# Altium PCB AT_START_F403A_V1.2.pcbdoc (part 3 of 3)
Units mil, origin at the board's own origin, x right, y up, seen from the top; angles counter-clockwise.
Board outline 5262.73 x 3522.74 mil, 2 copper layers (Top Layer, Bottom Layer); 135 components, 162 nets, 647 pads, 293 vias.
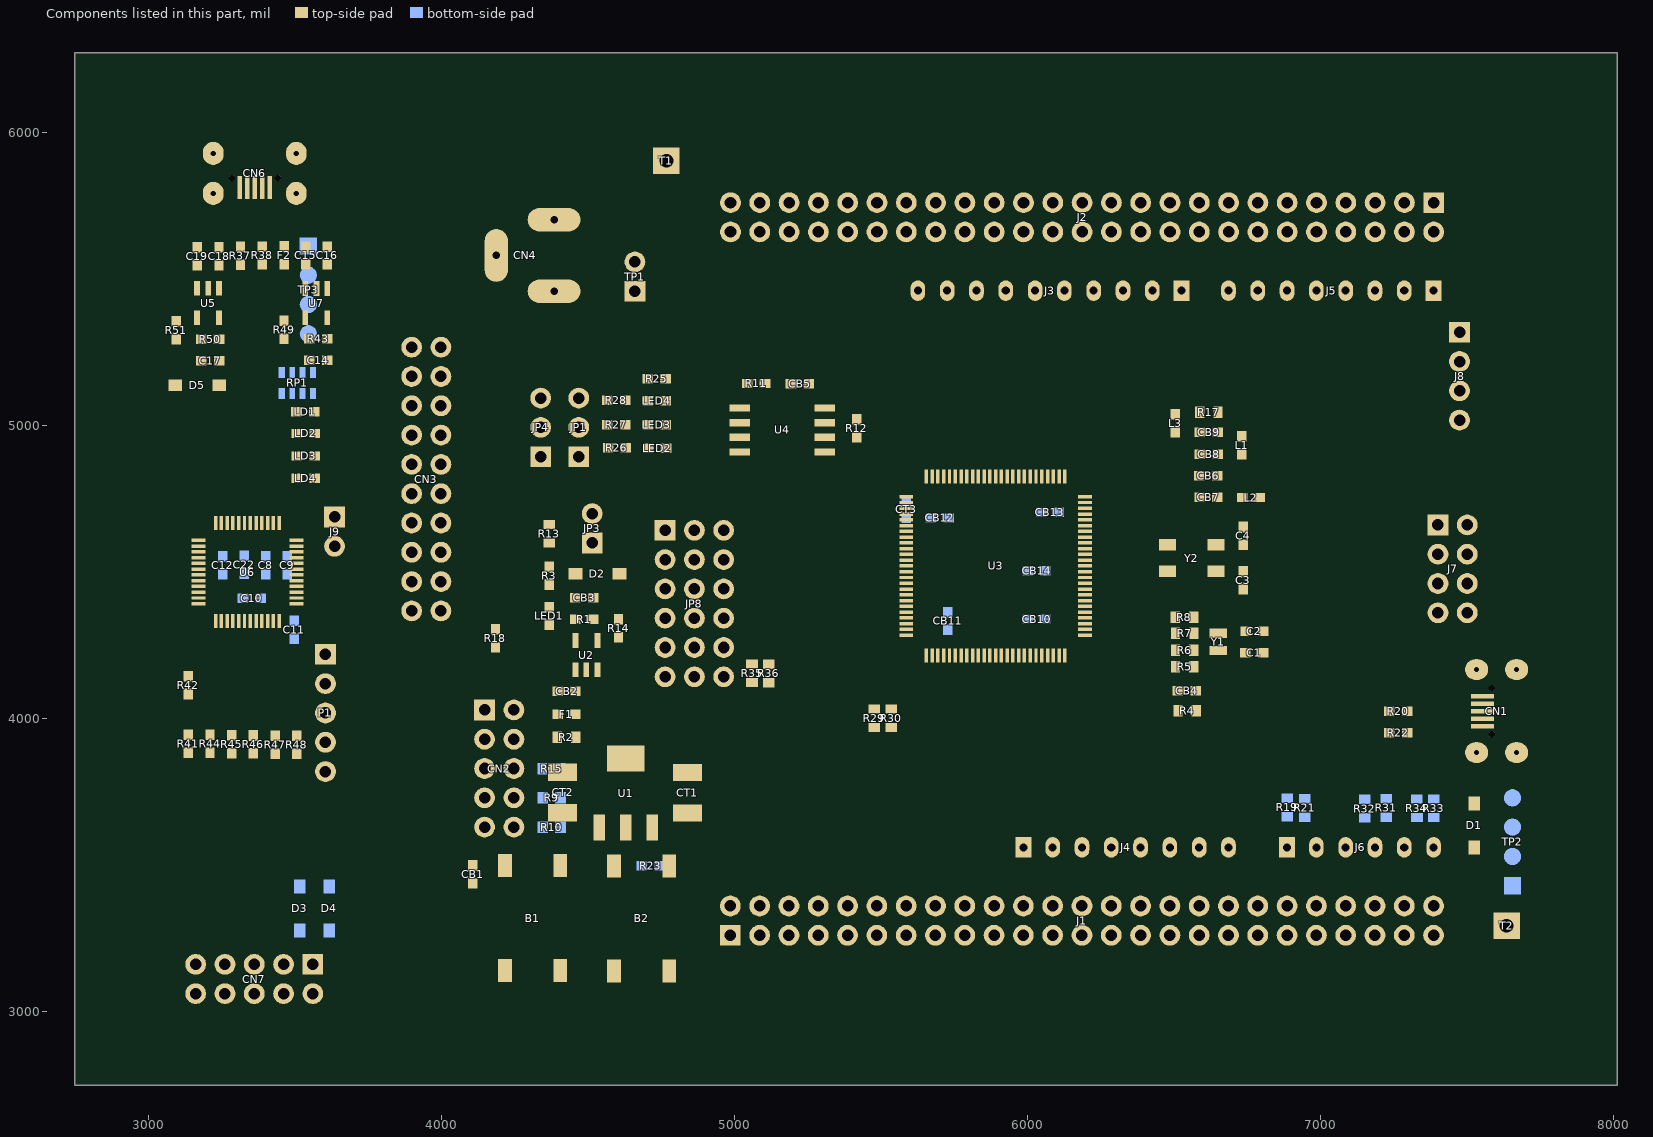
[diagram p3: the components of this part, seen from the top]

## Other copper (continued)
Bottom Layer:
  region net $1N764: 3255.85,5454.34 3480.85,5454.34 3480.85,5486.34 3255.85,5486.34
  region net 5V: 4998.13,3683.74 4993.99,3703.74 ccw(c4993.99,3674.68) 4981.13,3700.74 4981.13,3686.74 ccw(c4998.13,3733.41)
  region net ATLINK_5V: 3434.05,5682.34 3419.05,5652.34 ccw(c3419.05,5754.59) 3449.05,5656.84 3453.34,5677.84 ccw(c3434.05,5638.75)
  region net VCC: 3484.85,4619.34 cw(c3584.85,4619.34) 3504.85,4679.34 3444.85,4679.34 cw(c3364.85,4619.34) 3464.85,4619.34
  region net 5V: 7501.85,3464.74 7518.92,3453.53 ccw(c7498.37,3474.07) 7525.89,3464.74 7515.99,3474.64 ccw(c7536.97,3429.62)
  region net AVREF+: 6429.99,5591.74 cw(c6379.99,5591.74) 6419.99,5561.74 6449.99,5561.74 cw(c6489.99,5591.74) 6439.99,5591.74
  region net VDD: 5805.99,4571.74 cw(c5905.99,4571.74) 5825.99,4631.74 5765.99,4631.74 cw(c5685.99,4571.74) 5785.99,4571.74
  region net VDD: 5972.99,4687.74 cw(c5930.59,4687.74) 5952.99,4651.74 6012.99,4651.74 cw(c6035.39,4687.74) 5992.99,4687.74
  region net VDD: 4550.99,4690.76 cw(c4550.99,4590.76) 4610.99,4670.76 4610.99,4730.76 cw(c4550.99,4810.76) 4550.99,4710.76
  region net A0: 6907.7,3623.74 cw(c6907.7,3653.74) 6889.7,3629.74 6889.7,3611.74 cw(c6907.7,3587.74) 6907.7,3617.74
  region net JDI: 4987.99,3938.88 4987.43,3938.9 4986.87,3938.95 4986.32,3939.04 4985.79,3939.16 4985.27,3939.32 4984.77,3939.51 4984.3,3939.74 4983.87,3940 4983.46,3940.29 4983.1,3940.63 4982.78,3940.99 4982.51,3941.4 4982.29,3941.83 4982.13,3942.31 4982.03,3942.82 4981.99,3943.36 4975.99,3943.36 4975.92,3941.84 4975.71,3940.23 4975.36,3938.57 4974.88,3936.92 4974.27,3935.31 4973.53,3933.81 4973.12,3933.12 4972.68,3932.47 4972.21,3931.87 4971.71,3931.32 4975.95,3927.08 4977.13,3928.16 4978.48,3929.21 4979.95,3930.19 4981.52,3931.07 4983.14,3931.81 4983.96,3932.12 4984.79,3932.38 4985.6,3932.6 4986.41,3932.75 4987.21,3932.85 4987.99,3932.88
  region net NRST: 4082.83,3733.74 4082.08,3733.77 4081.26,3733.86 4079.51,3734.21 4077.66,3734.75 4075.79,3735.45 4073.96,3736.28 4072.27,3737.21 4070.79,3738.2 4070.15,3738.71 4069.59,3739.23 4065.35,3734.98 4065.86,3734.42 4066.37,3733.79 4067.36,3732.3 4068.29,3730.61 4069.12,3728.79 4069.82,3726.91 4070.36,3725.06 4070.71,3723.31 4070.8,3722.5 4070.83,3721.74 4076.83,3721.74 4076.87,3722.3 4076.97,3722.86 4077.13,3723.41 4077.35,3723.94 4077.62,3724.46 4077.94,3724.96 4078.3,3725.43 4078.71,3725.87 4079.15,3726.27 4079.62,3726.63 4080.11,3726.95 4080.63,3727.22 4081.17,3727.44 4081.71,3727.61 4082.27,3727.71 4082.83,3727.74
  region net VCC: 3390.85,4588.34 3384.85,4573.34 3416.85,4573.34 3410.85,4588.34
  region net VCC: 3446.85,4565.34 3416.85,4573.34 3416.85,4537.34 3446.85,4545.34
  region net VCC: 3520.85,4565.34 3490.85,4573.34 3490.85,4537.34 3520.85,4545.34
  region net VCC: 3464.85,4603.34 3458.85,4573.34 3490.85,4573.34 3484.85,4603.34
  region net VCC: 3428.85,4565.34 3428.85,4545.34 3458.85,4537.34 3458.85,4573.34
  region net VCC: 3313.37,4365.34 3333.37,4365.34 3341.37,4395.34 3305.37,4395.34
  region net VCC: 3275.37,4421.34 3275.37,4401.34 3305.37,4395.34 3305.37,4427.34
  region net VCC: 3452.43,4283.95 3452.43,4263.95 3482.43,4256.08 3482.43,4292.08
  region net VCC: 3488.43,4237.84 3508.43,4237.84 3514.43,4256.08 3482.43,4256.08
  region net VCC: 3243.85,4603.34 3237.85,4573.34 3269.85,4573.34 3263.85,4603.34
  region net 3V3: 3551.37,3227.77 3526.41,3197.77 3596.37,3197.77 3571.37,3227.77
  region net NRST: 3288.42,3185.78 3264.85,3222.58 3258.85,3222.58 3235.27,3185.78
  region net ATLK_TX: 3297.21,3060.12 3306.56,3102.81 3302.32,3107.05 3259.63,3097.7
  region net ATLK_RX: 3197.21,3060.12 3206.56,3102.81 3202.32,3107.05 3159.63,3097.7
  region net 3V3: 3607.37,3381.06 3627.37,3381.06 3637.05,3404.43 3597.68,3404.43
  region net 3V3: 3607.37,3481.68 3597.68,3451.68 3637.05,3451.68 3627.37,3481.68
  region net VCC: 3570.41,4699.34 3570.41,4679.34 3600.41,4654.34 3600.41,4724.34
  region net VCC: 3539.41,4230.34 3539.41,4210.34 3569.41,4185.34 3569.41,4255.34
  region net VCC: 3594.85,4285.77 3569.85,4255.77 3639.85,4255.77 3614.85,4285.77
  region net M-NRST: 3640.21,3918.12 3649.56,3960.81 3645.32,3965.05 3602.63,3955.7
  region net VCC: 3491.37,5193.06 3466.76,5201.76 3466.76,5164.35 3491.37,5173.06
  region net VCC: 3455.94,5193.06 3455.94,5173.06 3481.53,5164.35 3481.53,5201.76
  region net VCC: 3526.8,5193.06 3501.21,5201.76 3501.21,5164.35 3526.8,5173.06
  region net VCC: 3562.23,5193.06 3536.64,5201.76 3536.64,5164.35 3562.23,5173.06
  region net VCC: 3491.37,5193.06 3491.37,5173.06 3516.96,5164.35 3516.96,5201.76
  region net VCC: 3603.06,5193.06 3573.06,5201.76 3573.06,5164.35 3603.06,5173.06
  region net VCC: 3526.8,5193.06 3526.8,5173.06 3551.41,5164.35 3551.41,5201.76
  region net $1N750: 3452.94,5082.52 3458.94,5082.52 3466.44,5091.52 3445.44,5091.52
  region net $1N751: 3488.37,5082.52 3494.37,5082.52 3501.21,5091.52 3481.53,5091.52
  region net $1N752: 3523.8,5082.52 3529.8,5082.52 3536.64,5091.52 3516.96,5091.52
  region net $1N753: 3559.23,5082.52 3565.23,5082.52 3572.73,5091.52 3551.73,5091.52
  region net ATLINK_5V: 3483.43,5629.34 3483.43,5599.34 3516.9,5584.81 3516.9,5643.87
  region net USBM: 3565.96,5492.19 3593.43,5511.34 3593.43,5517.34 3565.96,5536.49
  region net USBP: 3564.35,5390.88 3596.39,5409.27 3596.81,5415.27 3567.46,5435.06
  region net VBUS: 7596.46,3441.06 7596.46,3421.06 7626.46,3401.21 7626.46,3460.27
  region net USB_M: 7636.46,3552.89 7605.79,3533.74 7605.79,3527.74 7636.46,3508.59
  region net USB_P: 7636.46,3652.89 7605.79,3633.74 7605.79,3627.74 7636.46,3608.59
  region net D2: 4434.08,3733.59 4425.08,3741.09 4425.08,3720.09 4434.08,3727.59
  region net ATLK_TX: 4318.84,3733.74 4318.84,3727.74 4327.84,3720.24 4327.84,3741.24
  region net D8: 4434.08,3633.74 4425.08,3641.24 4425.08,3620.24 4434.08,3627.74
  region net ATLK_RX: 4318.84,3633.74 4318.84,3627.74 4327.84,3620.24 4327.84,3641.24
  region net 5V: 4274.57,4054.18 4257.99,4074.43 4237.99,4074.43 4221.42,4054.18
  region net JTMS: 4124.55,3957.32 4088.99,3933.74 4088.99,3927.74 4124.55,3904.17
  region net JTMS: 4183.35,3928.52 4192.71,3971.21 4188.46,3975.45 4145.77,3966.1
  region net BOOT0: 4215.47,3944.8 4195.93,3899.9 4198.65,3894.13 4238.1,3896.72
  region net BOOT0: 4271.43,3904.17 4299.99,3927.74 4299.99,3933.74 4271.43,3957.32
  region net JTCK: 4124.55,3857.32 4087.75,3833.74 4087.75,3827.74 4124.55,3804.17
  region net JTCK: 4182.49,3822.64 4196.43,3866.56 4192.91,3871.52 4151.72,3865.98
  region net SWO: 4270.91,3803.72 4308.17,3827.06 4308.28,3833.06 4271.94,3856.86
  region net NRST: 4124.55,3757.32 4087.75,3733.74 4087.75,3727.74 4124.55,3704.17
  region net ATLK_TX: 4212.63,3732.96 4203.28,3690.27 4207.52,3686.03 4250.21,3695.38
  region net ATLK_TX: 4271.43,3704.17 4308.23,3727.74 4308.23,3733.74 4271.43,3757.32
  region net ATLK_RX: 4271.43,3604.17 4308.23,3627.74 4308.23,3633.74 4271.43,3657.32
  region net PB6: 4837.42,4120.3 4860.99,4100.74 4866.99,4100.74 4890.57,4120.3
  region net PB7: 4861.77,4208.38 4904.46,4199.03 4908.71,4203.27 4899.35,4245.96
  region net PA8: 4899.35,4541.52 4908.71,4584.21 4904.46,4588.45 4861.77,4579.1
  region net PB1_E: 4999.35,4641.52 5008.71,4684.21 5004.46,4688.45 4961.77,4679.1
  region net D7: 4987.05,4516.84 5024.18,4540.24 5024.27,4546.24 4987.8,4569.98
  region net D7: 4987.43,4517.17 5024.23,4540.74 5024.23,4546.74 4987.43,4570.31
  region net PB7_E: 4970.28,4208.87 5010.77,4204.69 5013.97,4209.98 4997.8,4254.34
  region net PB6_E: 4987.43,4117.17 5006.99,4140.74 5006.99,4146.74 4987.43,4170.31
  region net VIN: 4374.99,5389.74 4394.99,5389.74 4419.99,5419.74 4349.99,5419.74
  region net VIN: 4503.72,5469.74 4454.36,5494.74 4454.36,5424.74 4503.72,5449.74
  region net D2: 7451.85,5146.31 7416.99,5122.74 7416.99,5116.74 7451.85,5093.17
  region net VDD: 6110.03,4350.94 6080.03,4356.94 6080.03,4324.94 6110.03,4330.94
  region net VDD: 6072.02,4386.94 6052.02,4386.94 6044.03,4356.94 6080.03,4356.94
  region net VDD: 5774.95,4313.7 5745.2,4321.7 5745.2,4285.7 5774.95,4293.7
  region net VDD: 5683.2,4313.74 5683.2,4293.74 5713.2,4285.7 5713.2,4321.7
  region net VDD: 5660.99,4731.74 5652.99,4701.74 5688.99,4701.74 5680.99,4731.74
  region net VDD: 5660.99,4657.74 5680.99,4657.74 5688.99,4669.74 5652.99,4669.74
  region net VDD: 5625.99,4695.74 5625.99,4675.74 5652.99,4669.74 5652.99,4701.74
  region net VDD: 5999.99,4714.74 5999.99,4694.74 6028.99,4688.74 6028.99,4720.74
  region net VDD: 6036.99,4749.74 6028.99,4720.74 6064.99,4720.74 6056.99,4749.74
  region net VDD: 6110.03,4515.94 6080.03,4521.94 6080.03,4489.94 6110.03,4495.94
  region net VDD: 6052.03,4551.94 6044.03,4521.94 6080.03,4521.94 6072.03,4551.94
  region net VDD: 6072,4459.94 6080.03,4489.94 6044.03,4489.94 6052,4459.94
  region net NRST: 3896.77,4533.38 3939.46,4524.03 3943.71,4528.27 3934.35,4570.96
  region net D3: 3896.77,4633.38 3939.46,4624.03 3943.71,4628.27 3934.35,4670.96
  region net JTCK: 3896.77,4833.38 3939.46,4824.03 3943.71,4828.27 3934.35,4870.96
  region net JTMS: 3896.77,4933.38 3939.46,4924.03 3943.71,4928.27 3934.35,4970.96
  region net JDI: 3934.35,5066.52 3943.71,5109.21 3939.46,5113.45 3896.77,5104.1
  region net D5: 3875.55,5195.31 3848.99,5171.74 3848.99,5165.74 3875.55,5142.17
  region net VDD: 5625.84,4695.89 5603.33,4703.89 5603.33,4667.89 5625.84,4675.89
  region net VDD: 5557.56,4695.74 5557.56,4675.74 5571.33,4667.89 5571.33,4703.89
  region net PB9: 7213.27,3385.03 7189.7,3421.83 7183.7,3421.83 7160.12,3385.03
  region net PB8: 7222.06,3259.37 7231.41,3302.06 7227.17,3306.31 7184.48,3296.95
  region net D4: 6960.12,3238.15 6983.7,3206.04 6989.7,3206.04 7013.27,3238.15
  region net D5: 6884.48,3326.23 6927.17,3316.88 6931.41,3321.12 6922.06,3363.81
  region net D3: 6860.12,3238.15 6883.7,3201.35 6889.7,3201.35 6913.27,3238.15
  region net D3: 6888.91,3296.95 6846.22,3306.31 6841.98,3302.06 6851.33,3259.37
  region net PB2: 5551.76,5764.23 5542.41,5721.54 5546.65,5717.3 5589.34,5726.65
  region net PB1_E: 5660.55,5638.58 5684.12,5601.78 5690.12,5601.78 5713.7,5638.58
  region net D0_RX: 6188.74,5697.41 6146.19,5706.34 6142.02,5702.03 6151.8,5659.2
  region net D1_TX: 6213.41,5785.77 6189.7,5817.44 6183.7,5817.44 6160.27,5785.13
  region net AVREF+: 6384.3,5726.69 6425.69,5715.52 6432.88,5722.47 6422.52,5763.63
  region net NRST: 6784.3,5626.69 6827.13,5616.91 6831.45,5621.08 6822.52,5663.63
  region net PB8: 5623.69,5417.77 5629.69,5417.77 5637.19,5428.9 5616.19,5428.9
  region net PB9: 5723.69,5417.77 5729.69,5417.77 5737.19,5428.9 5716.19,5428.9
  region net AVREF+: 5821.69,5511.08 5809.19,5489.44 5844.19,5489.44 5831.69,5511.08
  region net D12: 6123.69,5417.77 6129.69,5417.77 6137.19,5428.9 6116.19,5428.9
  region net D11: 6223.69,5417.77 6229.69,5417.77 6237.19,5428.9 6216.19,5428.9
  region net D10: 6323.69,5417.77 6329.69,5417.77 6337.19,5428.9 6316.19,5428.9
  region net A0: 6883.7,3605.59 6876.2,3596.59 6897.2,3596.59 6889.7,3605.59
  region net A1: 6983.7,3605.41 6976.2,3594.28 6997.2,3594.28 6989.7,3605.41
  region net A2: 7083.7,3605.41 7076.2,3594.28 7097.2,3594.28 7089.7,3605.41
  region net A3: 7155.39,3579.59 7155.33,3571.16 7161.7,3554.19 7163.85,3581.73
  region net A4: 7260.01,3592.52 7257.03,3587.01 7261.7,3571.74 7271.61,3591.53
  region net A5: 7383.99,3605.44 7376.49,3594.41 7397.49,3594.14 7389.99,3605.37
  region net 5V: 7525.13,4635.59 7547.57,4652.17 7547.57,4672.17 7525.13,4688.74
  region net NRST: 7378.26,4488.74 7341.46,4465.17 7341.46,4459.17 7378.26,4435.59
  region net $3N822: 4680.99,3524.09 4673.49,3515.09 4694.49,3515.09 4686.99,3524.09
  region net $3N822: 4656.99,3502.09 4656.99,3496.09 4665.99,3488.59 4665.99,3509.59
  region net D5: 6883.69,5417.77 6889.69,5417.77 6897.19,5428.9 6876.19,5428.9
  region net D4: 6983.69,5417.77 6989.69,5417.77 6997.19,5428.9 6976.19,5428.9
  region net D3: 7083.69,5417.77 7089.69,5417.77 7097.19,5428.9 7076.19,5428.9
  region net D2: 7183.69,5417.77 7189.69,5417.77 7197.19,5428.9 7176.19,5428.9
  region net D1_TX: 7283.69,5505.41 7276.19,5494.28 7297.19,5494.28 7289.69,5505.41
  region net D0_RX: 7383.69,5505.59 7376.19,5496.59 7397.19,5496.59 7389.69,5505.59
  region net M-NRST: 3324.35,4583.38 3316.85,4574.38 3337.85,4574.38 3330.35,4583.38
  region net 5V: 3506.37,3481.68 3496.68,3451.68 3536.05,3451.68 3526.37,3481.68
  region net ATLINK_5V: 3470.37,3294.06 3470.37,3264.06 3496.68,3254.43 3496.68,3301.68
  region net 3V3: 4504.99,4535.33 4524.99,4535.33 4549.99,4565.33 4479.99,4565.33
  region net VDD: 4538.43,4674.19 4575.23,4690.76 4575.23,4710.76 4538.43,4727.34
  region net VIN: 4595.56,5469.74 4595.56,5449.74 4625.56,5424.74 4625.56,5494.74
  region net VIN: 6676.69,3624.5 6661.69,3571.59 6711.69,3571.59 6696.69,3624.5
  region net 5V: 6376.69,3624.5 6361.69,3571.59 6411.69,3571.59 6396.69,3624.5
  region net 3V3: 6276.69,3508.44 6296.69,3508.44 6311.69,3551.59 6261.69,3551.59
  region net NRST: 6183.69,3605.41 6176.19,3594.28 6197.19,3594.28 6189.69,3605.41
  region net 3V3: 6076.69,3498.68 6096.69,3498.68 6111.69,3551.59 6061.69,3551.59
  region net $1N753: 3463.18,4812.48 3475.45,4818.34 3475.45,4824.34 3463.18,4830.2
  region net $1N752: 3463.18,4888.2 3475.45,4894.06 3475.45,4900.06 3463.18,4905.91
  region net $1N751: 3463.18,4965.39 3475.45,4971.24 3475.45,4977.24 3463.18,4983.1
  region net $1N750: 3464.93,5056.47 3458.94,5068.53 3452.94,5068.31 3447.23,5055.82
  region net M-NRST: 3333.18,4744.2 3345.45,4750.06 3345.45,4756.06 3333.18,4761.91
  region net PB11_E: 5241.64,4781.55 5235.79,4793.82 5229.79,4793.82 5223.93,4781.55
  region net PB11_E: 5238.58,4848.79 5234.05,4835.98 5238.29,4831.74 5251.11,4836.27
  region net PB8: 5274.16,4729.32 5278.69,4742.13 5274.45,4746.37 5261.63,4741.84
  region net PB9: 5270.16,4681.32 5274.69,4694.13 5270.45,4698.37 5257.63,4693.84
  region net M-NRST: 3318.74,4604.06 3324.35,4591.44 3330.35,4591.09 3336.43,4603.02
  region net SPIM_IO3: 5174.52,5011.79 5169.99,4998.98 5174.23,4994.74 5187.05,4999.27
  region net NRST: 5140.37,3649.69 5152.64,3655.55 5152.64,3661.55 5140.37,3667.41
  region net NRST: 5141.4,4064.57 5154.18,4070.06 5154.69,4076.06 5142.9,4082.22
  region net PB9: 6049.18,4031.6 6036.91,4025.74 6036.91,4019.74 6049.18,4013.88
  region net PB11: 5702.99,4901.2 5715.26,4907.06 5715.26,4913.06 5702.99,4918.91
  region net PB1: 5918.88,5038.91 5906.62,5033.06 5906.62,5027.06 5918.88,5021.2
  region net A3: 5952.8,5181.88 5965.07,5187.74 5965.07,5193.74 5952.8,5199.6
  region net PB8: 5070.51,4255.24 5076.37,4242.98 5082.37,4242.98 5088.23,4255.24
  region net PB9: 5102.51,4255.24 5108.37,4242.98 5114.37,4242.98 5120.23,4255.24
  region net D10: 5328.23,4747.87 5322.37,4760.13 5316.37,4760.13 5310.51,4747.87
  region net D9: 5369.54,4505.53 5356.72,4510.06 5352.48,4505.82 5357.01,4493
  region net PA11: 5485.53,4118.25 5497.88,4124.06 5497.97,4130.06 5485.78,4135.97
  region net NRST: 6225.56,4081.91 6213.29,4076.06 6213.29,4070.06 6225.56,4064.2
  region net NRST: 6242.23,4080.87 6236.37,4093.13 6230.37,4093.13 6224.51,4080.87
  region net PA12: 5542.84,4088.25 5555.19,4094.05 5555.27,4100.06 5543.09,4105.97
  region net PA11: 6146.56,4135.91 6134.29,4130.06 6134.29,4124.06 6146.56,4118.2
  region net PA12: 6173.56,4105.91 6161.29,4100.06 6161.29,4094.06 6173.56,4088.2
  region net PB12: 6198.56,4058.6 6186.29,4052.74 6186.29,4046.74 6198.56,4040.88
  region net M-USB_DM: 3350.04,4248.2 3337.77,4242.34 3337.77,4236.34 3350.04,4230.48
  region net NRST: 3300.06,3450.08 3295.53,3437.26 3299.77,3433.02 3312.59,3437.55
  region net ATLK_TX: 3334.06,3419.08 3329.53,3406.26 3333.77,3402.02 3346.59,3406.55
  region net NRST: 3319.66,3629.48 3331.93,3635.34 3331.93,3641.34 3319.66,3647.2
  region net ATLK_TX: 3353.66,3594.48 3365.93,3600.34 3365.93,3606.34 3353.66,3612.2
  region net JTCK: 3144.66,3658.48 3156.93,3664.34 3156.93,3670.34 3144.66,3676.2
  region net JTCK: 3634.59,3640.13 3621.77,3644.66 3617.53,3640.42 3622.06,3627.6
  region net BOOT0: 3292.66,3684.48 3304.93,3690.34 3304.93,3696.34 3292.66,3702.2
  region net BOOT0: 3638.11,3679.84 3625.29,3684.37 3621.05,3680.13 3625.58,3667.32
  region net JTMS: 3218.58,3717.57 3230.84,3723.42 3230.84,3729.42 3218.58,3735.28
  region net M-USB_DP: 3350.04,4205.2 3337.77,4199.34 3337.77,4193.34 3350.04,4187.48
  region net USBP: 3326.64,5709.6 3331.17,5722.42 3326.92,5726.66 3314.11,5722.13
  region net USBM: 3372.24,5701.48 3384.51,5707.34 3384.51,5713.34 3372.24,5719.2
  region net M-USB_DM: 3354.64,5264.08 3350.11,5251.26 3354.35,5247.02 3367.17,5251.55
  region net M-USB_DP: 3321.64,5264.08 3317.11,5251.26 3321.35,5247.02 3334.17,5251.55
  region net D12: 6023.8,5365.88 6036.07,5371.74 6036.07,5377.74 6023.8,5383.6
  region net D11: 6008.8,5330.88 6019.99,5336.74 6019.99,5342.74 6008.8,5348.6
  region net USB_P: 7360.8,4017.88 7373.07,4023.74 7373.07,4029.74 7360.8,4035.6
  region net USB_M: 7350.13,3975.93 7355.99,3963.66 7361.99,3963.66 7367.85,3975.93
  region net PC0: 6698.8,5159.88 6711.07,5165.74 6711.07,5171.74 6698.8,5177.6
  region net PC1: 6644.8,5153.88 6657.07,5159.74 6657.07,5165.74 6644.8,5171.6
  region net A2: 6098.48,5156 6103.01,5168.82 6098.77,5173.06 6085.96,5168.53
  region net A0: 6304.8,5097.88 6316.99,5103.74 6316.99,5109.74 6304.8,5115.6
  region net PB11: 7163.78,4187 7168.31,4199.82 7164.07,4204.06 7151.25,4199.53
  region net PB2: 5242.85,5325.87 5236.99,5338.13 5230.99,5338.13 5225.13,5325.87
  region net NRST: 4225.8,3380.88 4238.07,3386.74 4238.07,3392.74 4225.8,3398.6
  region net NRST: 4828.18,3398.6 4815.91,3392.74 4815.91,3386.74 4828.18,3380.88
  region net $3N822: 4642.8,3490.23 4655.07,3496.09 4655.07,3502.09 4642.8,3507.95
  region net D5: 5887.18,3901.6 5874.91,3895.74 5874.91,3889.74 5887.18,3883.88
  region net BOOT0: 6033.18,3871.6 6020.91,3865.74 6020.91,3859.74 6033.18,3853.88
  region net PD15: 5688.8,4500.88 5701.07,4506.74 5701.07,4512.74 5688.8,4518.6
  region net PD14: 5688.8,4537.88 5701.07,4543.74 5701.07,4549.74 5688.8,4555.6
  region net PD13: 5673.18,4589.97 5660.91,4584.11 5660.91,4578.11 5673.18,4572.25
  region net D8: 6518.18,5297.6 6505.91,5291.74 6505.91,5285.74 6518.18,5279.88
  region net D8: 6533.8,5279.88 6546.07,5285.74 6546.07,5291.74 6533.8,5297.6
  region net D7: 6678.18,5322.6 6665.91,5316.74 6665.91,5310.74 6678.18,5304.88
  region net JDI: 5671.73,3928.53 5658.91,3933.06 5654.67,3928.82 5659.2,3916
  region net AVREF+: 6790.18,5359.6 6777.91,5355.74 6777.91,5345.74 6790.18,5341.88
  region net D8: 7276.18,5314.6 7263.91,5308.74 7263.91,5302.74 7276.18,5296.88
  region net PC3: 6329.66,4950.6 6317.39,4944.74 6317.39,4938.74 6329.66,4932.88
  region net PC1: 6372.18,4906.6 6359.91,4900.74 6359.91,4894.74 6372.18,4888.88
  region net PC0: 6396.18,4882.6 6383.91,4876.74 6383.91,4870.74 6396.18,4864.88
  region net PB15: 7290.18,5192.6 7277.91,5186.74 7277.91,5180.74 7290.18,5174.88
  region net PC13: 6895.8,4130.88 6908.07,4136.74 6908.07,4142.74 6895.8,4148.6
  region net VDD: 6436.42,5052.87 6418.24,5049.74 6418.24,5029.74 6436.42,5026.62
  region net PB14: 7289.91,5224.3 7278.49,5217.93 7279.42,5211.93 7292.63,5206.79
  region net VDD: 6619.42,4040.94 6601.24,4037.82 6601.24,4017.82 6619.42,4014.69
  region net PC1: 6101.8,4590.73 6114.07,4596.58 6114.07,4602.58 6101.8,4608.44
  region net PC3: 6112.8,4651.88 6125.07,4657.74 6125.07,4663.74 6112.8,4669.6
  region net PC2: 6111.8,4619.88 6124.07,4625.74 6124.07,4631.74 6111.8,4637.6
  region net PC0: 6116.8,4564.88 6129.07,4570.74 6129.07,4576.74 6116.8,4582.6
  region net NRST: 5942.23,4301.93 5948.09,4289.66 5954.09,4289.66 5959.94,4301.93
  region net 5V: 7512.02,3475.62 7502.09,3464.98 7516.23,3450.84 7526.87,3460.77
  region net 5V: 7536.49,3484 7535.99,3498.54 7515.99,3498.54 7515.49,3484
  region net SPIM_IO3: 4991.78,4804 4996.31,4816.82 4992.07,4821.06 4979.25,4816.53
  region net PB6: 5954.85,3895.55 5948.99,3907.82 5942.99,3907.82 5937.13,3895.55
  region net PB6_E: 5978.88,3919.6 5966.68,3913.74 5966.68,3907.74 5978.88,3901.88
  region net PB7_E: 6027.85,3931.55 6021.99,3943.82 6015.99,3943.82 6010.13,3931.55
  region net PB8: 6022.18,4006.6 6009.91,4000.74 6009.91,3994.74 6022.18,3988.88
  region net A1: 6280.8,5124.88 6293.07,5130.74 6293.07,5136.74 6280.8,5142.6
  region net D9: 6414.91,5315.18 6410.38,5302.37 6414.62,5298.12 6427.43,5302.66
  region net D6: 6753.2,5292.48 6748.67,5279.66 6752.91,5275.42 6765.73,5279.95
  region net D2: 7178.88,5304.6 7166.62,5298.74 7166.62,5292.74 7178.88,5286.88
  region net PB13: 7270.18,5282.6 7257.91,5276.74 7257.91,5270.74 7270.18,5264.88
  region net D3: 6722.25,3439.95 6735.07,3435.42 6739.31,3439.66 6734.78,3452.48
  region net BOOT0: 4056.58,4179.79 4052.05,4166.98 4056.29,4162.74 4069.11,4167.27
  region net JTMS: 3671.11,3699.84 3658.29,3704.37 3654.05,3700.13 3658.58,3687.32
  region net D2: 5522.56,3848.91 5510.29,3843.06 5510.29,3837.06 5522.56,3831.2
  region net PB7: 5960.21,3964.91 5948.71,3959.06 5948.71,3953.06 5960.21,3947.2
  region net JDI: 4970.13,4048.86 4975.99,4036.6 4981.99,4036.6 4987.85,4048.86
  region net D2: 5453.85,4376.55 5447.99,4388.82 5441.99,4388.82 5436.13,4376.55
  region net D7: 5385.64,4382.91 5373.37,4377.06 5373.37,4371.06 5385.64,4365.2
  region net D7: 5402.31,4381.87 5396.45,4394.13 5390.45,4394.13 5384.59,4381.87
  region net PA8: 5371.05,4421.84 5358.24,4426.37 5353.99,4422.13 5358.53,4409.32
  region net PB13: 5417.23,4769.87 5411.37,4782.13 5405.37,4782.13 5399.51,4769.87
  region net PB14: 5444.23,4736.87 5438.37,4749.13 5432.37,4749.13 5426.51,4736.87
  region net PB15: 5475.23,4710.55 5469.37,4722.82 5463.37,4722.82 5457.51,4710.55
  region net D6: 5623.18,5098.2 5635.45,5104.06 5635.45,5110.06 5623.18,5115.91
  region net PD15: 5512.51,4995.24 5518.37,4982.98 5524.37,4982.98 5530.23,4995.24
  region net PB1: 5451.23,4880.87 5445.37,4893.13 5439.37,4893.13 5433.51,4880.87
  region net PD13: 5454.51,4992.24 5460.37,4979.98 5466.37,4979.98 5472.23,4992.24
  region net PD14: 5483.51,4960.24 5489.37,4947.98 5495.37,4947.98 5501.23,4960.24
  region net D3: 5860.56,3815.91 5848.29,3810.06 5848.29,3804.06 5860.56,3798.2
  region net JTCK: 5641.56,3841.91 5629.29,3836.06 5629.29,3830.06 5641.56,3824.2
  region net JTMS: 5608.56,3897.91 5596.29,3892.06 5596.29,3886.06 5608.56,3880.2
  region net PB12: 5161.18,4026.2 5173.45,4032.06 5173.45,4038.06 5161.18,4043.91
  region net D8: 5461.56,3823.91 5449.29,3818.06 5449.29,3812.06 5461.56,3806.2
  region net LD4: 3147.23,4335.87 3141.37,4348.13 3135.37,4348.13 3129.51,4335.87
  region net LD4: 3129.51,4710.53 3135.37,4698.26 3141.37,4698.26 3147.23,4710.53
  region net SWO: 3173.63,3801.27 3186.45,3796.74 3190.69,3800.98 3186.16,3813.79
  region net SWO: 3175.11,3824.84 3162.29,3829.37 3158.05,3825.13 3162.58,3812.32
  region net SWO: 3127.31,4016.24 3133.16,4003.98 3139.16,4003.98 3145.02,4016.24
  region net SWO: 4031.32,3729.68 4019.06,3723.82 4019.06,3717.82 4031.32,3711.96
  region net ATLK_RX: 3499.04,3539.91 3486.77,3534.05 3486.77,3528.05 3499.04,3522.2

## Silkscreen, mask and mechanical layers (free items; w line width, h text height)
Top Silkscreen Layer:
  drawing of 1272 lines, arcs and shapes, not listed
  text "49" at 4956.37,5940.06 h36
  text "41" at 5362.37,5940.06 h36
  text "31" at 5862.37,5940.06 h36
  text "21" at 6362.37,5940.06 h36
  text "11" at 6865.37,5940.06 h36
  text "1" at 7380.37,5940.06 h36
  text "B10*" at 5066.37,5827.06 h36 r45
  text "E14" at 5166.37,5827.06 h36 r45
  text "E12" at 5266.37,5827.06 h36 r45
  text "E10" at 5366.37,5827.06 h36 r45
  text "E8" at 5471.37,5827.06 h36 r45
  text "B2" at 5571.37,5827.06 h36 r45
  text "B0" at 5671.37,5827.06 h36 r45
  text "A6" at 5871.37,5827.06 h36 r45
  text "A4" at 5971.37,5827.06 h36 r45
  text "A2" at 6171.37,5827.06 h36 r45
  text "A0" at 6271.37,5827.06 h36 r45
  text "NC" at 6476.37,5827.06 h36 r45
  text "NC" at 6771.37,5827.06 h36 r45
  text "E6" at 7171.37,5827.06 h36 r45
  text "E4" at 7271.37,5827.06 h36 r45
  text "E2" at 7371.37,5827.06 h36 r45
  text "GND" at 4971.37,5823.06 h36 r45
  text "C4" at 5771.37,5823.06 h36 r45
  text "GND" at 6071.37,5823.06 h36 r45
  text "C2" at 6571.37,5823.06 h36 r45
  text "C0" at 6671.37,5823.06 h36 r45
  text "C15" at 6971.37,5823.06 h36 r45
  text "C13" at 7071.37,5823.06 h36 r45
  text "VREF" at 6366.37,5819.06 h36 r45
  text "VDD" at 6871.37,5819.06 h36 r45
  text "GND" at 4707.37,5762.06 h48
  text "A1" at 6293.37,5536.06 h36 r45
  text "C1" at 6693.37,5536.06 h36 r45
  text "E9" at 5489.5,5533.06 h36 r45
  text "A3" at 6184.37,5527.06 h36 r45
  text "NC" at 6385.37,5527.06 h36 r45
  text "NC" at 6484.37,5527.06 h36 r45
  text "C3" at 6584.37,5527.06 h36 r45
  text "NC" at 6884.37,5527.06 h36 r45
  text "E3" at 7384.37,5527.06 h36 r45
  text "E7" at 5584.37,5523.06 h36 r45
  text "C5" at 5784.37,5523.06 h36 r45
  text "A7" at 5884.37,5523.06 h36 r45
  text "A5" at 5984.37,5523.06 h36 r45
  text "E5" at 7285.37,5523.06 h36 r45
  text "B1*" at 5670.37,5515.97 h34 r45
  text "NRST" at 6769.37,5515.06 h25 r45
  text "GND" at 6973.37,5515.06 h32 r45
  text "E11" at 5377.37,5514.06 h36 r45
  text "C14" at 7070.37,5514.06 h34 r45
  text "VBAT" at 7169.37,5512.06 h25 r45
  text "VDD" at 6069.37,5508.14 h36 r45
  text "E13" at 5268.37,5506.06 h36 r45
  text "VDD" at 4963.99,5501.79 h36 r45
  text "E15" at 5168.37,5502.06 h36 r45
  text "B11*" at 5062.37,5489.55 h36 r45
  text "50" at 4956.37,5447.29 h36
  text "VIN (7V-12V)" at 4646.37,5443.74 h48 r90
  text "4" at 7011.99,5351.74 h48 r90
  text "8" at 6550.99,5350.74 h48 r90
  text "7" at 6714.99,5350.74 h48 r90
  text "2" at 7208.99,5350.74 h48 r90
  text "13" at 6048.99,5309.74 h48 r90
  text "12" at 6148.99,5309.74 h48 r90
  text "#6" at 6810.99,5303.74 h48 r90
  text "#5" at 6911.99,5303.74 h48 r90
  text "#9" at 6449.99,5302.74 h48 r90
  text "#3" at 7110.99,5302.74 h48 r90
  text "BOOT1" at 4179.37,5282.06 h48
  text "BOOT0" at 4424.37,5282.06 h48
  text "#11" at 6248.99,5262.74 h48 r90
  text "#10" at 6349.99,5262.74 h48 r90
  text "SCL" at 5648.99,5252.74 h48 r90
  text "SDA" at 5748.99,5252.74 h48 r90
  text "GND" at 5949.7,5252.74 h48 r90
  text "GND" at 4292.37,5221.06 h36
  text "GND" at 4421.37,5221.06 h36
  text "DIGITAL(#=PWM)" at 6398.99,5208.74 h48
  text "TX 1" at 7311.99,5207.74 h48 r90
  text "RX 0" at 7412.99,5207.74 h48 r90
  text "AREF" at 5849.7,5205.74 h48 r90
  text "LD:" at 3643,5166.25 h36 r270
  text "AT-Link-EZ V1.4" at 3043.43,5064.34 h60 r270
  text "1" at 3645.17,5049.94 h36 r270
  text "2" at 3644.17,4982.94 h36 r270
  text "3" at 3643.17,4909.94 h36 r270
  text "4" at 3644.17,4834.94 h36 r270
  text "VDD" at 4292.37,4786.06 h36
  text "VDD" at 4422.37,4786.06 h36
  text "SPIM" at 4722.37,4742.06 h36
  text "IO*" at 4894.37,4742.06 h36
  text "MISO" at 7160.37,4638.06 h48
  text "5V" at 7579.37,4638.06 h48
  text "IDD" at 4637.37,4591.06 h48 r90
  text "SCK" at 7195.37,4538.06 h48
  text "MOSI" at 7579.37,4538.06 h48
  text "RESET" at 7099.37,4438.06 h48
  text "GND" at 7579.37,4438.06 h48
  text "20-pin ARM standard JTAG" at 4198.37,4393.06 h36 r90
  text "NSS" at 7195.37,4338.06 h48
  text "PB11" at 7579.37,4338.06 h48
  text "Micro USB" at 7438.37,3867.06 h48 r90
  text "POWER" at 6489.25,3783.53 h48
  text "ANALOG IN" at 7006.99,3768.74 h48
  text "AT-START-F403A V1.2" at 4974.37,3671.51 h55
  text "AT-Link" at 3975.37,3670.06 h48 r90
  text "IOREF" at 6110.7,3636.74 h48 r90
  text "RESET" at 6208.7,3636.74 h48 r90
  text "3.3V" at 6309.7,3636.74 h48 r90
  text "5V" at 6409.7,3636.74 h48 r90
  text "GND" at 6510.7,3636.74 h48 r90
  text "GND" at 6609.99,3636.74 h48 r90
  text "VIN" at 6709.7,3636.74 h48 r90
  text "AN0" at 6911.37,3626.06 h48 r90
  text "AN1" at 7011.37,3625.06 h48 r90
  text "AN2" at 7110.37,3625.06 h48 r90
  text "AN3" at 7210.37,3625.06 h48 r90
  text "AN4" at 7310.37,3625.06 h48 r90
  text "AN5" at 7411.37,3625.06 h48 r90
  text "3V3" at 3536.37,3592.06 h36 r270
  text "GND" at 3142.37,3590.06 h36 r270
  text "SWC" at 3341.37,3590.06 h36 r270
  text "SWD" at 3443.37,3590.06 h36 r270
  text "NRST" at 3239.37,3589.06 h36 r270
  text "52" at 4956.37,3540.06 h36
  text "68" at 5756.37,3540.06 h36
  text "BOOT0" at 3443.37,3461.06 h36 r270
  text "SWO" at 3341.37,3435.06 h36 r270
  text "B13" at 4971.37,3432.06 h36 r45
  text "B15" at 5071.37,3432.06 h36 r45
  text "D9" at 5171.37,3432.06 h36 r45
  text "D11" at 5271.37,3432.06 h36 r45
  text "A9" at 5771.37,3432.06 h36 r45
  text "A11" at 5871.37,3432.06 h36 r45
  text "D1" at 6471.37,3432.06 h36 r45
  text "D3" at 6571.37,3432.06 h36 r45
  text "D5" at 6671.37,3432.06 h36 r45
  text "D7" at 6771.37,3432.06 h36 r45
  text "B4" at 6871.37,3432.06 h36 r45
  text "B9" at 7171.37,3432.06 h36 r45
  text "E1" at 7271.37,3432.06 h36 r45
  text "D15" at 5471.37,3431.29 h36 r45
  text "A13" at 5971.37,3429.61 h32 r45
  text "A14" at 6171.37,3429.61 h32 r45
  text "D13" at 5361.37,3428.06 h30 r45
  text "C7" at 5571.37,3428.06 h36 r45
  text "C9" at 5671.37,3428.06 h36 r45
  text "B6*" at 6966.37,3428.06 h32 r45
  text "BOOT0" at 7061.37,3428.06 h20 r45
  text "GND" at 6071.37,3425.74 h32 r45
  text "C10" at 6271.37,3425.06 h34 r45
  text "C12" at 6371.37,3425.06 h34 r45
  text "VDD" at 7371.37,3421.06 h34 r45
  text "TX" at 3241.37,3415.06 h36 r270
  text "5V" at 3537.37,3415.06 h36 r270
  text "RX" at 3140.37,3413.06 h36 r270
  text "GND" at 7570.37,3391.06 h48
  text "D8" at 5184.37,3132.06 h36 r45
  text "C8" at 5684.37,3132.06 h36 r45
  text "NC" at 6084.37,3132.06 h36 r45
  text "D0" at 6484.37,3132.06 h36 r45
  text "D2" at 6584.37,3132.06 h36 r45
  text "D4" at 6684.37,3132.06 h36 r45
  text "B3" at 6884.37,3132.06 h36 r45
  text "B8" at 7184.37,3132.06 h36 r45
  text "E0" at 7284.37,3132.06 h36 r45
  text "B5" at 6984.37,3128.59 h36 r45
  text "C6" at 5584.37,3128.06 h36 r45
  text "D6" at 6784.37,3128.06 h36 r45
  text "C11" at 6376.37,3119.06 h36 r45
  text "B12" at 4968.37,3111.06 h36 r45
  text "B14" at 5068.37,3111.06 h36 r45
  text "D10" at 5268.37,3111.06 h36 r45
  text "D12" at 5368.37,3111.06 h36 r45
  text "D14" at 5468.37,3111.06 h36 r45
  text "A10" at 5868.37,3111.06 h36 r45
  text "A12" at 5968.37,3111.06 h36 r45
  text "A8*" at 5764.37,3107.06 h36 r45
  text "VDD" at 6164.37,3107.06 h36 r45
  text "A15" at 6268.37,3107.06 h36 r45
  text "B7*" at 7064.37,3107.06 h36 r45
  text "GND" at 7364.37,3107.06 h36 r45
  text "51" at 4962.37,3052.06 h36
  text "61" at 5462.37,3052.06 h36
  text "71" at 5962.37,3052.06 h36
  text "81" at 6462.37,3052.06 h36
  text "91" at 6962.37,3052.06 h36
  text "99" at 7356.37,3052.06 h36
  text "USER" at 4598.37,3030.06 h48
  text "RESET" at 4203.37,3029.06 h48
Bottom Silkscreen Layer:
  drawing of 295 lines, arcs and shapes, not listed
  text "29" at 5979.84,5827.06 h36 r315
  text "27" at 6079.84,5827.06 h36 r315
  text "25" at 6179.84,5827.06 h36 r315
  text "23" at 6279.84,5827.06 h36 r315
  text "21" at 6379.84,5827.06 h36 r315
  text "NC" at 6479.84,5827.06 h36 r315
  text "17" at 6579.84,5827.06 h36 r315
  text "15" at 6679.84,5827.06 h36 r315
  text "NC" at 6779.84,5827.06 h36 r315
  text "11" at 6879.84,5827.06 h36 r315
  text "7" at 7069.26,5827.06 h36 r315
  text "1" at 7369.26,5827.06 h36 r315
  text "39" at 5479.46,5823.06 h36 r315
  text "37" at 5579.84,5823.06 h36 r315
  text "35" at 5679.84,5823.06 h36 r315
  text "33" at 5779.84,5823.06 h36 r315
  text "31" at 5879.84,5823.06 h36 r315
  text "9" at 6969.26,5823.06 h36 r315
  text "5" at 7169.26,5823.06 h36 r315
  text "3" at 7269.26,5823.06 h36 r315
  text "49" at 4979.84,5815.06 h36 r315
  text "47" at 5079.84,5815.06 h36 r315
  text "45" at 5179.84,5815.06 h36 r315
  text "43" at 5279.84,5815.06 h36 r315
  text "41" at 5379.84,5815.06 h36 r315
  text "2" at 7369.26,5551.06 h36 r315
  text "8" at 7069.26,5548.06 h36 r315
  text "6" at 7169.26,5548.06 h36 r315
  text "4" at 7266.41,5537.06 h42 r315
  text "28" at 6079.84,5532.06 h36 r315
  text "26" at 6179.84,5532.06 h36 r315
  text "24" at 6279.84,5532.06 h36 r315
  text "NC" at 6375.84,5532.06 h36 r315
  text "NC" at 6475.84,5532.06 h36 r315
  text "18" at 6579.84,5532.06 h36 r315
  text "16" at 6679.84,5532.06 h36 r315
  text "14" at 6779.84,5532.06 h36 r315
  text "NC" at 6875.84,5532.06 h36 r315
  text "10" at 6979.84,5532.06 h36 r315
  text "50" at 4971.84,5528.06 h36 r315
  text "38" at 5579.84,5528.06 h36 r315
  text "36" at 5679.84,5528.06 h36 r315
  text "34" at 5779.84,5528.06 h36 r315
  text "32" at 5879.84,5528.06 h36 r315
  text "30" at 5979.84,5528.06 h36 r315
  text "40" at 5479.46,5527.06 h36 r315
  text "48" at 5079.84,5519.06 h36 r315
  text "46" at 5179.84,5519.06 h36 r315
  text "44" at 5279.84,5519.06 h36 r315
  text "42" at 5379.84,5519.06 h36 r315
  text "3V3" at 7391.27,5300.84 h36
  text "3V3" at 4144.81,5246.48 h36
  text "3V3" at 4286.77,5246.48 h36
  text "USART1_TX" at 7372.1,5204.13 h36
  text "NJTRST" at 4229.87,5155.88 h36
  text "GND" at 4362.36,5155.88 h36
  text "AT32F403AVGT7" at 6760.81,5144.06 h120
  text "USART1_RX" at 7372.1,5103.9 h36
  text "JTDI" at 4164.06,5049.34 h36
  text "GND" at 4286.87,5049.08 h36
  text "GND" at 7391.27,5003.35 h36
  text "JTMS" at 4164.06,4951.06 h36
  text "GND" at 4286.51,4951.04 h36
  text "JTCK" at 4164.06,4851.06 h36
  text "GND" at 4286.15,4851.04 h36
  text "NC" at 4147.97,4751.04 h36
  text "GND" at 4286.51,4751.04 h36
  text "VDD" at 3520.8,4657.34 h36 r270
  text "JTDO" at 4164.06,4648.06 h36
  text "GND" at 4286.87,4648.04 h36
  text "NRST" at 4164.06,4554.06 h36
  text "GND" at 4286.77,4554.38 h36
  text "NC" at 4147.97,4451.04 h36
  text "GND" at 4286.15,4451.04 h36
  text "M-BOOT0" at 3519.8,4377.34 h36 r270
  text "NC" at 4147.97,4349.04 h36
  text "GND" at 4286.77,4349.04 h36
  text "VDD" at 3536.88,4179.42 h36
  text "M-SWDIO" at 3524.57,4102.06 h36
  text "3V3" at 4079.22,4014.06 h36
  text "E5V" at 4402.22,4014.06 h36
  text "M-SWCLK" at 3524.57,4002.06 h36
  text "SWDIO" at 4072.9,3914.06 h36
  text "BOOT0" at 4467.85,3913.74 h36
  text "M-NRST" at 3527.74,3902.06 h36
  text "SWCLK" at 4072.9,3814.06 h36
  text "SWO" at 4546.22,3811.06 h36
  text "GND" at 3537.22,3802.06 h36
  text "NRST" at 4076.06,3714.06 h36
  text "USART1_RX" at 4737.25,3711.2 h36
  text "GND" at 4079.22,3614.06 h36
  text "USART1_TX" at 4738.25,3611.06 h36
  text "70" at 5879.84,3432.06 h36 r315
  text "72" at 5979.84,3432.06 h36 r315
  text "74" at 6079.84,3432.06 h36 r315
  text "76" at 6179.84,3432.06 h36 r315
  text "78" at 6279.84,3432.06 h36 r315
  text "52" at 4979.84,3428.06 h36 r315
  text "54" at 5079.84,3428.06 h36 r315
  text "56" at 5179.84,3428.06 h36 r315
  text "58" at 5279.84,3428.06 h36 r315
  text "60" at 5379.84,3428.06 h36 r315
  text "62" at 5479.84,3428.06 h36 r315
  text "64" at 5579.84,3428.06 h36 r315
  text "66" at 5679.84,3428.06 h36 r315
  text "68" at 5779.84,3428.06 h36 r315
  text "80" at 6379.84,3428.06 h36 r315
  text "82" at 6479.84,3428.06 h36 r315
  text "84" at 6579.84,3428.06 h36 r315
  text "86" at 6679.84,3428.06 h36 r315
  text "88" at 6779.84,3428.06 h36 r315
  text "90" at 6879.84,3428.06 h36 r315
  text "92" at 6979.84,3428.06 h36 r315
  text "94" at 7079.84,3428.06 h36 r315
  text "96" at 7179.84,3428.06 h36 r315
  text "98" at 7279.84,3428.06 h36 r315
  text "100" at 7389.61,3427.06 h36 r315
  text "71" at 5979.84,3137.06 h36 r315
  text "NC" at 6079.84,3137.06 h36 r315
  text "75" at 6179.84,3137.06 h36 r315
  text "77" at 6279.84,3137.06 h36 r315
  text "79" at 6375.84,3137.06 h36 r315
  text "51" at 4979.84,3133.06 h36 r315
  text "53" at 5079.84,3133.06 h36 r315
  text "55" at 5179.84,3133.06 h36 r315
  text "57" at 5279.84,3133.06 h36 r315
  text "59" at 5379.84,3133.06 h36 r315
  text "61" at 5479.84,3133.06 h36 r315
  text "63" at 5579.84,3133.06 h36 r315
  text "65" at 5679.84,3133.06 h36 r315
  text "67" at 5779.84,3133.06 h36 r315
  text "69" at 5879.84,3133.06 h36 r315
  text "81" at 6479.84,3133.06 h36 r315
  text "83" at 6576.84,3133.06 h36 r315
  text "85" at 6676.84,3133.06 h36 r315
  text "87" at 6779.84,3133.06 h36 r315
  text "89" at 6879.84,3133.06 h36 r315
  text "91" at 6979.84,3133.06 h36 r315
  text "93" at 7074.84,3133.06 h36 r315
  text "95" at 7179.84,3133.06 h36 r315
  text "97" at 7279.46,3133.06 h36 r315
  text "99" at 7379.84,3132.59 h36 r315
Mechanical Layer:
  lines w1 net "": 3790.37,3023.06 cw(c3845.26,3077.95) 3767.63,3077.95 3767.63,3079.34 3767.19,3079.78 3767.19,3518.06 3728.11,3518.06 3728.11,3077.96 cw(c3650.47,3077.96) 3705.37,3023.06 cw(c3651.16,3077.27) 3651.16,3000.6 3649.37,3000.6 3844.58,3000.6 cw(c3844.58,3077.27) 3790.37,3023.06 ; 3790.37,3023.06 3790.37,3023.06 ; 3727.68,4898.56 3767.19,4898.56 3767.19,5549.16 3767.37,5549.34 3728.37,5549.34 3727.68,4898.56 ; 3728.37,3602.34 3767.37,3602.34 3767.37,3694.34 3728.37,3694.34 3728.37,3602.34 ; 3728.37,3811.06 3767.37,3811.06 3767.37,4821.34 3728.37,4821.34 3728.37,3811.06 ; 3826.07,3123.89 ccw(c3891.07,3123.89) 3891.07,3058.89 ccw(c3891.07,3121.88) 3954.07,3121.88 3954.07,3125.9 ccw(c3891.07,3125.9) 3891.07,3188.89 3886.07,3188.89 ccw(c3886.07,3128.89) 3826.07,3128.89 3826.07,3123.89 ; 3826.07,5898.89 ccw(c3891.07,5898.89) 3891.07,5833.89 ccw(c3891.07,5896.88) 3954.07,5896.88 3954.07,5900.9 ccw(c3891.07,5900.9) 3891.07,5963.89 3886.07,5963.89 ccw(c3886.07,5903.89) 3826.07,5903.89 3826.07,5898.89 ; 5371.7,3561.59 ccw(c5436.7,3561.59) 5436.7,3496.59 ccw(c5436.7,3559.58) 5499.69,3559.58 5499.69,3563.6 ccw(c5436.7,3563.6) 5436.7,3626.59 5431.7,3626.59 ccw(c5431.7,3566.59) 5371.7,3566.59 5371.7,3561.59 ; 5421.7,5461.59 ccw(c5486.7,5461.59) 5486.7,5396.59 ccw(c5486.7,5459.58) 5549.69,5459.58 5549.69,5463.6 ccw(c5486.7,5463.6) 5486.7,5526.59 5481.7,5526.59 ccw(c5481.7,5466.59) 5421.7,5466.59 5421.7,5461.59 ; 7421.7,4861.59 ccw(c7486.7,4861.59) 7486.7,4796.59 ccw(c7486.7,4859.58) 7549.69,4859.58 7549.69,4863.6 ccw(c7486.7,4863.6) 7486.7,4926.59 7481.7,4926.59 ccw(c7481.7,4866.59) 7421.7,4866.59 7421.7,4861.59 ; 7572.7,5897.59 ccw(c7637.7,5897.59) 7637.7,5832.59 ccw(c7637.7,5895.58) 7700.69,5895.58 7700.69,5899.6 ccw(c7637.7,5899.6) 7637.7,5962.59 7632.7,5962.59 ccw(c7632.7,5902.59) 7572.7,5902.59 7572.7,5897.59 ; 7573.7,3123.59 ccw(c7638.7,3123.59) 7638.7,3058.59 ccw(c7638.7,3121.58) 7701.69,3121.58 7701.69,3125.6 ccw(c7638.7,3125.6) 7638.7,3188.59 7633.7,3188.59 ccw(c7633.7,3128.59) 7573.7,3128.59 7573.7,3123.59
